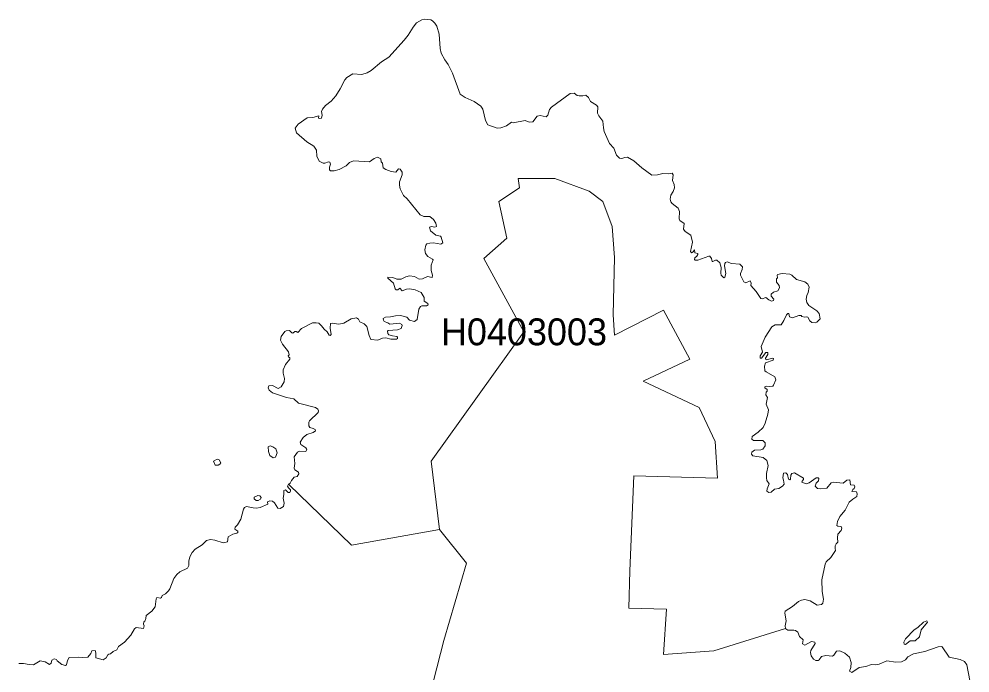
# Model space of a CAD drawing. Extents: x 369010 to 739155, y 6377141 to 6616555.
# Drawn here: x 422472 to 426007, y 6493936 to 6496369 of the extents above; entities that cross this region are included whole.
import ezdxf
from ezdxf.enums import TextEntityAlignment as Align

# ---------------------------------------------------------------- set-up
doc = ezdxf.new("R2010")
doc.units = 0
doc.header["$LTSCALE"] = 40
doc.layers.add('1', color=7, linetype='Continuous', lineweight=13)
doc.layers.add('2', color=7, linetype='Continuous')

msp = doc.modelspace()

# ---------------------------------------------------------------- linework, layer by layer
at = {"layer": '1'}
for points in [[(424682.77, 6495887.95), (424666.88, 6495905.17), (424646.53, 6495950.51), (424643.71, 6495963.92), (424642.39, 6495988.75), (424626.5, 6496008.77), (424622.36, 6496018.54), (424623.69, 6496042.37), (424618.89, 6496048.16), (424595.39, 6496062.06), (424588.6, 6496076.46), (424578.34, 6496085.4), (424567.91, 6496082.75), (424553.84, 6496082.75), (424546.23, 6496084.74), (424535.31, 6496092.68), (424520.25, 6496092.19), (424450.74, 6496040.88), (424443.12, 6496032.6), (424436.83, 6496010.76), (424430.71, 6496005.3), (424408.37, 6496009.6), (424398.27, 6496007.94), (424382.05, 6495986.43), (424367.65, 6495985.27), (424352.92, 6495991.73), (424309.06, 6495983.12), (424302.28, 6495984.61), (424283.41, 6495971.04), (424262.23, 6495963.92), (424248.66, 6495962.6), (424214.73, 6495974.68), (424205.13, 6495991.06), (424196.19, 6496032.94), (424187.75, 6496044.19), (424163.59, 6496062.06), (424130.32, 6496076.46), (424111.45, 6496088.88), (424083.48, 6496167.82), (424066.6, 6496199.27), (424054.02, 6496216.98), (424040.45, 6496241.47), (424037.14, 6496259.18), (424034, 6496312.14), (424024.56, 6496341.6), (424017.12, 6496353.35), (424008.34, 6496362.29), (424002.39, 6496365.1), (423980.04, 6496368.74), (423969.45, 6496366.26), (423949.75, 6496354.01), (423936.51, 6496338.62), (423918.47, 6496309.16), (423903.41, 6496290.13), (423845.98, 6496227.24), (423819.01, 6496209.03), (423780.61, 6496176.59), (423765.71, 6496168.48), (423746.52, 6496162.86), (423712.92, 6496165.17), (423690.24, 6496151.11), (423682.8, 6496142.5), (423665.75, 6496108.9), (423649.86, 6496082.92), (423632.15, 6496063.22), (423610.64, 6496047), (423599.55, 6496032.94), (423596.57, 6496024.16), (423598.39, 6496011.09), (423595.41, 6496000.5), (423586.8, 6495998.84), (423585.32, 6496000.17), (423585.98, 6496008.44), (423563.63, 6496001.99), (423542.45, 6496001.16), (423508.85, 6495977), (423498.26, 6495963.09), (423503.56, 6495945.22), (423541.46, 6495911.62), (423567.44, 6495896.23), (423577.21, 6495880.34), (423578.36, 6495858), (423587.47, 6495839.46), (423601.87, 6495832.68), (423608.98, 6495832.35), (423621.89, 6495836.98), (423627.19, 6495836.81), (423629.84, 6495829.04), (423625.37, 6495817.95), (423625.2, 6495808.18), (423629.01, 6495803.71), (423642.58, 6495803.71), (423661.94, 6495808.51), (423687.93, 6495822.91), (423700.01, 6495835.32), (423715.24, 6495840.62), (423773.82, 6495836.98), (423791.53, 6495850.39), (423804.44, 6495854.36), (423816.03, 6495848.9)], [(425399.57, 6495340.8), (425404.87, 6495351.56), (425408.34, 6495371.42), (425404.2, 6495382.67), (425392.12, 6495390.61), (425362, 6495400.05), (425343.8, 6495415.94), (425336.68, 6495419.74), (425308.38, 6495421.73), (425291, 6495417.92), (425289.51, 6495415.94), (425291, 6495406.5), (425287.19, 6495402.03), (425287.52, 6495390.28), (425297.29, 6495377.21), (425298.45, 6495368.44), (425292.82, 6495358.18), (425275.94, 6495352.22), (425267.17, 6495345.43), (425267.5, 6495338.15), (425277.43, 6495326.56), (425276.27, 6495321.1), (425268.99, 6495319.61), (425259.22, 6495324.25), (425247.97, 6495333.19), (425233.9, 6495328.39), (425228.94, 6495329.54), (425212.05, 6495355.2), (425191.86, 6495377.87), (425193.19, 6495386.64), (425189.38, 6495395.25), (425173.82, 6495386.97), (425165.88, 6495391.11), (425154.13, 6495415.61), (425153.8, 6495422.39), (425159.92, 6495437.45), (425160.58, 6495447.38), (425151.48, 6495456.82), (425120.53, 6495458.8), (425103.98, 6495465.09), (425098.19, 6495463.27), (425095.54, 6495459.8), (425094.22, 6495450.36), (425099.51, 6495422.06), (425095.54, 6495407.99), (425091.07, 6495406.17), (425082.13, 6495415.61), (425080.48, 6495422.72), (425081.31, 6495443.91), (425076.34, 6495462.11), (425065.75, 6495471.55), (425060.78, 6495471.55), (425051.02, 6495466.25), (425048.37, 6495467.08), (425046.05, 6495477.5), (425039.43, 6495486.28), (425036.29, 6495486.61), (424995.57, 6495471.55), (424984.98, 6495472.21), (424982.67, 6495474.53), (424983.33, 6495480.32), (424990.94, 6495486.61), (424994.91, 6495492.9), (424994.58, 6495496.7), (424984.32, 6495498.85), (424982.33, 6495509.94), (424977.87, 6495502.83), (424971.41, 6495498.69), (424968.27, 6495503.99), (424974.72, 6495538.74), (424969.09, 6495564.56), (424947.58, 6495578.13), (424941.95, 6495587.56), (424944.1, 6495607.59), (424927.88, 6495619.18), (424926.06, 6495625.3), (424926.73, 6495652.44), (424921.93, 6495665.35), (424899.58, 6495682.73), (424895.11, 6495688.69), (424892.3, 6495698.95), (424895.11, 6495713.02), (424903.39, 6495727.25), (424907.86, 6495740.82), (424906.7, 6495753.73), (424901.07, 6495767.8), (424903.06, 6495789.31), (424899.09, 6495795.27), (424887, 6495792.96), (424864.33, 6495794.28), (424844.8, 6495788.98), (424824.28, 6495787.49), (424787.37, 6495815.63), (424757.58, 6495841.45), (424733.42, 6495855.02), (424723.49, 6495854.19), (424712.23, 6495850.39), (424703.79, 6495850.55), (424692.21, 6495862.14), (424682.77, 6495887.95)], [(423816.03, 6495848.9), (423817.85, 6495837.97), (423822.48, 6495832.01), (423824.8, 6495814.64), (423834.56, 6495809.01), (423854.59, 6495802.06), (423872.63, 6495798.42), (423881.73, 6495810.83), (423888.68, 6495810.17), (423896.13, 6495798.75), (423896.13, 6495788.98), (423886.04, 6495763.16), (423885.54, 6495750.09), (423888.68, 6495737.18), (423901.43, 6495712.52), (423914.67, 6495700.11), (423962.17, 6495640.86), (423976.57, 6495634.73), (423999.24, 6495634.07), (424012.81, 6495622.98), (424020.43, 6495609.91), (424023.07, 6495596.67), (424017.78, 6495594.68), (424005.36, 6495597.33), (423996.92, 6495594.68), (424000.9, 6495580.45), (424021.25, 6495564.39), (424037.8, 6495560.42), (424040.78, 6495557.77), (424046.57, 6495535.76), (424039.29, 6495530.8), (424011.82, 6495536.26), (423998.91, 6495535.43), (423987.66, 6495531.96), (423983.35, 6495527.49), (423980.7, 6495509.78), (423982.69, 6495496.87), (423991.79, 6495484.79), (424008.84, 6495476.02), (424011.32, 6495472.7), (424003.05, 6495453.34), (424003.38, 6495433.81), (424008.84, 6495415.61), (424007.52, 6495407.33), (423990.14, 6495410.81), (423971.77, 6495402.86), (423959.52, 6495400.88), (423941.81, 6495411.47), (423922.94, 6495413.45), (423910.03, 6495409.65), (423892.33, 6495400.88), (423876.44, 6495401.21), (423860.71, 6495406.67), (423843.17, 6495408.82), (423843.17, 6495404.35), (423863.69, 6495386.15), (423869.98, 6495364.96), (423873.79, 6495361.16), (423879.25, 6495361.65), (423887.03, 6495366.95), (423896.46, 6495357.85), (423911.69, 6495363.97), (423924.76, 6495365.13), (423944.13, 6495360.82), (423965.97, 6495351.39), (423978.22, 6495333.35), (423977.73, 6495318.62), (423991.63, 6495310.18), (423992.46, 6495305.05), (423986, 6495301.24), (423968.79, 6495301.57), (423963.82, 6495299.26), (423958.2, 6495289.49), (423951.41, 6495251.59), (423941.15, 6495244.14), (423923.44, 6495247.95), (423913.51, 6495259.2), (423890.01, 6495265.33), (423871.14, 6495265), (423852.27, 6495260.36), (423834.23, 6495260.03), (423825.13, 6495255.07), (423825.96, 6495248.28), (423828.94, 6495243.81), (423842.51, 6495238.52), (423850.12, 6495233.22), (423886.37, 6495237.03), (423894.97, 6495232.06), (423896.46, 6495228.26), (423892.66, 6495217), (423878.75, 6495212.37), (423844, 6495210.05), (423841.68, 6495207.07), (423842.18, 6495198.46), (423846.65, 6495193.83), (423859.89, 6495189.69), (423876.44, 6495187.87), (423879.08, 6495184.89), (423877.93, 6495180.59), (423874.29, 6495177.94)], [(423473.93, 6494638.07), (423474.59, 6494637.57), (423707.13, 6494411.82), (424035.16, 6494469.42), (424003.87, 6494724.3), (424348.62, 6495205.08), (424199.67, 6495477.34), (424284.74, 6495553.97), (424254.94, 6495690.18), (424331.57, 6495741.15), (424327.27, 6495775.25), (424463.48, 6495775.25), (424591.08, 6495728.41), (424642.22, 6495690.18), (424676.15, 6495596.5), (424684.76, 6495481.64), (424680.46, 6495268.8), (424684.76, 6495192.34), (424867.64, 6495285.85), (424965.62, 6495102.97), (424791.18, 6495022.04), (424999.55, 6494924.22), (425059.13, 6494796.62), (425067.73, 6494660.41), (424757.08, 6494668.85), (424742.19, 6494315.83), (424737.89, 6494177.47), (424878.4, 6494173.17), (424867.64, 6494005.18), (425054.99, 6494017.92), (425321.29, 6494101.34), (425321.45, 6494101.5), (425319.96, 6494110.94), (425323.93, 6494129.81), (425317.98, 6494158.27), (425319.3, 6494166.05), (425346.44, 6494183.43), (425368.62, 6494201.97), (425380.37, 6494207.26), (425392.12, 6494209.25), (425412.15, 6494204.28), (425438.46, 6494188.39), (425454.19, 6494190.55), (425459.15, 6494195.84), (425461.97, 6494210.24), (425457.17, 6494239.53), (425456.17, 6494282.07), (425467.92, 6494340.82), (425472.06, 6494349.26), (425488.78, 6494365.65), (425506.49, 6494391.96), (425505.82, 6494399.08), (425505.82, 6494408.85), (425508.64, 6494416.29), (425515.42, 6494422.91), (425513.77, 6494438.3), (425515.75, 6494451.88), (425527.5, 6494466.28), (425529.82, 6494474.55), (425528.17, 6494480.51), (425515.75, 6494481.67), (425511.62, 6494484.48), (425513.93, 6494500.2), (425522.54, 6494518.08), (425542.23, 6494542.24), (425557.96, 6494571.37), (425571.2, 6494582.96), (425585.93, 6494592.06), (425587.58, 6494601.99), (425584.44, 6494610.26), (425567.89, 6494611.26), (425570.54, 6494618.87), (425576.49, 6494621.85), (425578.81, 6494628.3), (425576.49, 6494634.76), (425561.93, 6494636.58), (425559.94, 6494654.78), (425548.69, 6494653.63), (425534.95, 6494642.7), (425499.2, 6494646.51), (425490.43, 6494643.03), (425474.87, 6494623.83), (425451.54, 6494621.19), (425439.79, 6494622.68), (425430.68, 6494630.62), (425435.32, 6494642.37), (425443.59, 6494651.47), (425444.26, 6494659.25), (425442.1, 6494662.4), (425434.49, 6494662.23), (425409.17, 6494643.36), (425397.42, 6494639.72), (425382.03, 6494645.35), (425382.36, 6494649.16), (425387.32, 6494655.61), (425387.32, 6494660.91), (425354.06, 6494680.44), (425344.13, 6494678.29), (425341.15, 6494671.5), (425339.66, 6494656.6)], [(426006.64, 6493908.53), (425995.55, 6493965.96), (425986.78, 6493978.37), (425970.06, 6493986.48), (425929.35, 6493995.09), (425903.2, 6494033.48), (425899.56, 6494035.14), (425887.81, 6494033.81), (425838.82, 6494015.61), (425796.78, 6494007.5), (425776.09, 6493995.75), (425766.33, 6493985.49), (425752.59, 6493978.04), (425731.07, 6493976.71), (425697.48, 6493981.68), (425669.01, 6493968.6), (425654.61, 6493966.29), (425640.38, 6493967.28), (425620.02, 6493959.83), (425594.2, 6493956.19), (425567.23, 6493937.66), (425558.78, 6493942.62), (425563.58, 6493956.19), (425565.57, 6493975.06), (425559.28, 6493995.42), (425541.41, 6494009.98), (425523.37, 6494018.26), (425510.29, 6494017.26), (425500.53, 6494002.2), (425495.4, 6493998.89), (425471.23, 6494000.55), (425455.18, 6493997.07), (425446.41, 6493985.32), (425441.77, 6493982.67), (425433.33, 6493982.67), (425425.06, 6493987.14), (425416.29, 6493999.88), (425414.3, 6494012.3), (425415.29, 6494020.24), (425431.02, 6494046.23), (425429.69, 6494051.19), (425417.94, 6494053.18), (425392.12, 6494039.77), (425383.68, 6494044.41), (425386, 6494059.96), (425372.59, 6494072.38), (425366.63, 6494088.1), (425358.19, 6494093.89), (425351.74, 6494095.55), (425329.73, 6494095.22), (425321.62, 6494100.84), (425321.45, 6494101.5), (425321.29, 6494101.34), (425054.99, 6494017.92), (424867.64, 6494005.18), (424878.4, 6494173.17), (424737.89, 6494177.47), (424742.19, 6494315.83), (424757.08, 6494668.85), (425067.73, 6494660.41), (425059.13, 6494796.62), (424999.55, 6494924.22), (424791.18, 6495022.04), (424965.62, 6495102.97), (424867.64, 6495285.85), (424684.76, 6495192.34), (424680.46, 6495268.8), (424684.76, 6495481.64), (424676.15, 6495596.5), (424642.22, 6495690.18), (424591.08, 6495728.41), (424463.48, 6495775.25), (424327.27, 6495775.25), (424331.57, 6495741.15), (424254.94, 6495690.18), (424284.74, 6495553.97), (424199.67, 6495477.34), (424348.62, 6495205.08), (424003.87, 6494724.3), (424035.16, 6494469.42), (424135.45, 6494344.13), (424050.22, 6494056.82), (423846.31, 6493258.43)], [(425339.66, 6494656.6), (425337.34, 6494654.12), (425332.54, 6494656.6), (425327.91, 6494674.81), (425322.61, 6494680.11), (425313.67, 6494679.78), (425311.03, 6494661.57), (425314, 6494653.96), (425315.49, 6494638.56), (425309.87, 6494630.62), (425295.47, 6494622.18), (425280.08, 6494619.7), (425267.5, 6494608.77), (425258.56, 6494607.45), (425251.94, 6494612.91), (425252.44, 6494621.52), (425260.71, 6494639.23), (425251.94, 6494652.14), (425249.79, 6494662.23), (425250.45, 6494678.62), (425256.57, 6494707.58), (425251.61, 6494726.61), (425237.71, 6494737.54), (425199.81, 6494744.32), (425195.01, 6494749.95), (425195.34, 6494757.23), (425205.93, 6494764.35), (425229.43, 6494765.84), (425236.55, 6494768.49), (425245.15, 6494781.23), (425245.15, 6494791.99), (425236.55, 6494800.59), (425201.46, 6494800.59), (425195.67, 6494805.89), (425197.16, 6494815.32), (425219.83, 6494831.54), (425237.38, 6494849.42), (425244.82, 6494865.97), (425254.59, 6494898.9), (425257.24, 6494914.79), (425249.29, 6494935.48), (425253.6, 6494961.13), (425247.47, 6494970.23), (425248.63, 6494980.5), (425252.11, 6494984.3), (425252.11, 6494990.59), (425243.83, 6494996.22), (425243.83, 6495000.85), (425249.46, 6495003.5), (425260.05, 6495001.68), (425273.62, 6495003.5), (425276.6, 6495006.15), (425284.54, 6495026.18), (425281.57, 6495037.93), (425248.63, 6495056.3), (425244.49, 6495060.43), (425242.18, 6495077.48), (425246.81, 6495089.89), (425275.28, 6495099.49), (425276.6, 6495105.62), (425271.3, 6495106.61), (425251.61, 6495100.49), (425246.31, 6495103.13), (425246.48, 6495106.94), (425255.75, 6495121.01), (425255.75, 6495126.64), (425253.6, 6495128.62), (425247.47, 6495128.62), (425231.58, 6495107.44), (425227.11, 6495107.77), (425226.78, 6495115.22), (425235.89, 6495129.62), (425230.42, 6495150.8), (425244.82, 6495185.89), (425269.48, 6495223.62), (425281.9, 6495230.57), (425305.23, 6495231.73), (425315.16, 6495247.12), (425325.09, 6495268.14), (425329.56, 6495272.94), (425332.87, 6495272.94), (425335.19, 6495260.36), (425346.77, 6495256.89), (425370.28, 6495265.66), (425379.38, 6495265.99), (425381.7, 6495262.68), (425392.29, 6495260.03), (425400.56, 6495261.52), (425404.2, 6495260.03), (425411.16, 6495245.63), (425419.1, 6495239.68), (425431.02, 6495239.18), (425436.81, 6495241.16), (425450.05, 6495253.58), (425445.75, 6495272.78), (425436.81, 6495283.7), (425408.01, 6495303.06), (425400.23, 6495314.32), (425397.91, 6495327.23), (425399.57, 6495340.8)], [(423874.29, 6495177.94), (423853.43, 6495177.28), (423835.23, 6495182.25), (423822.15, 6495181.42), (423805.44, 6495174.63), (423779.78, 6495176.95), (423773, 6495191.18), (423765.05, 6495224.45), (423754.46, 6495234.38), (423738.9, 6495241.83), (423733.61, 6495251.76), (423726.16, 6495257.05), (423706.8, 6495253.25), (423678.99, 6495237.36), (423660.12, 6495234.21), (423635.96, 6495237.36), (423629.84, 6495236.2), (423628.68, 6495218.82), (423632.15, 6495194.66), (423627.85, 6495190.85), (423624.21, 6495192.67), (423616.93, 6495204.75), (423605.34, 6495215.35), (423595.74, 6495227.92), (423585.65, 6495236.86), (423575.88, 6495239.18), (423562.97, 6495238.52), (423522.26, 6495217.17), (423508.19, 6495202.27), (423502.07, 6495206.74), (423497.27, 6495206.41), (423489.65, 6495200.62), (423485.52, 6495201.44), (423477.57, 6495210.05), (423464.66, 6495209.39), (423460.19, 6495206.41), (423446.62, 6495187.54), (423443.48, 6495174.63), (423450.76, 6495159.57), (423473.77, 6495130.77), (423475.26, 6495119.52), (423472.61, 6495116.04), (423473.43, 6495112.57), (423478.73, 6495108.43), (423478.73, 6495103.13), (423461.68, 6495083.27), (423453.74, 6495063.91), (423453.74, 6495051), (423457.88, 6495031.47), (423456.72, 6495018.56), (423446.29, 6495000.85), (423435.2, 6494994.4), (423414.02, 6495004.99), (423400.45, 6495004.16), (423397.8, 6494997.38), (423401.27, 6494987.94), (423414.18, 6494978.18), (423465.82, 6494961.46), (423493.13, 6494955.84), (423510.51, 6494940.28), (423574.23, 6494924.22), (423582.67, 6494916.94), (423584.82, 6494910.82), (423583.99, 6494904.53), (423551.55, 6494874.24), (423549.4, 6494869.44), (423548.9, 6494856.04), (423552.71, 6494849.42), (423564.79, 6494845.94), (423572.07, 6494841.31), (423573.23, 6494836.84), (423564.79, 6494830.38), (423540.96, 6494823.27), (423527.89, 6494811.52), (423517.13, 6494794.64), (423519.44, 6494786.19), (423537.98, 6494774.11), (423541.79, 6494767.66), (423537.15, 6494760.21), (423514.64, 6494761.37), (423506.2, 6494757.56), (423494.95, 6494739.69), (423497.1, 6494715.69), (423494.95, 6494697.48), (423497.1, 6494691.86), (423510.01, 6494683.09), (423511.17, 6494676.3), (423505.21, 6494667.53), (423493.79, 6494664.88), (423484.36, 6494652.14), (423479.56, 6494641.87), (423474.26, 6494638.56), (423473.93, 6494638.07)], [(423473.93, 6494638.07), (423469.63, 6494631.45), (423472.94, 6494624.5), (423480.55, 6494617.05), (423481.05, 6494613.24), (423478.23, 6494607.62), (423471.94, 6494607.45), (423462.01, 6494617.05), (423456.06, 6494615.39), (423456.06, 6494599.67), (423453.08, 6494586.76), (423457.22, 6494567.4), (423455.23, 6494555.81), (423442.32, 6494547.37), (423433.38, 6494549.36), (423420.8, 6494569.05), (423414.02, 6494575.51), (423403.43, 6494576.5), (423394.82, 6494572.86), (423396.31, 6494563.76), (423367.51, 6494551.34), (423354.44, 6494549.36), (423341.53, 6494550.02), (423317.36, 6494555.48), (423309.75, 6494551.18), (423305.94, 6494546.05), (423296.51, 6494507.82), (423283.27, 6494486.96), (423275.16, 6494478.69), (423274, 6494470.74), (423284.43, 6494463.3), (423284.43, 6494458.99), (423281.45, 6494456.34), (423265.89, 6494452.7), (423249.51, 6494442.94), (423246.36, 6494424.07), (423230.64, 6494420.76), (423199.19, 6494430.53), (423183.64, 6494432.51), (423167.91, 6494428.37), (423152.52, 6494412.32), (423126.21, 6494396.93), (423115.28, 6494383.85), (423106.84, 6494368.3), (423102.54, 6494352.57), (423102.87, 6494335.53), (423097.74, 6494326.42), (423068.94, 6494312.03), (423057.85, 6494302.92), (423046.77, 6494287.86), (423032.04, 6494248.8), (423027.57, 6494241.19), (423016.48, 6494230.43), (423004.07, 6494223.98), (423001.75, 6494217.36), (422997.11, 6494213.88), (422984.37, 6494217.36), (422981.23, 6494212.23), (422977.25, 6494181.77), (422965.5, 6494166.38), (422944.32, 6494149.83), (422943.33, 6494139.07), (422939.35, 6494129.31), (422935.38, 6494126.33), (422933.89, 6494117.72), (422936.71, 6494111.27), (422933.89, 6494102.17), (422907.41, 6494105.31), (422901.45, 6494100.84), (422887.05, 6494076.35), (422864.21, 6494050.2), (422841.04, 6494034.48), (422834.59, 6494022.39), (422821.51, 6494016.6), (422812.08, 6494006.84), (422805.79, 6494006.17), (422802.15, 6494003.53), (422795.7, 6493992.44), (422784.11, 6493985.65), (422757.3, 6493992.93), (422757.46, 6494010.97), (422754.49, 6494020.24), (422742.4, 6494017.92), (422738.6, 6494008.82), (422727.84, 6493995.09), (422707.48, 6493993.1), (422691.26, 6493994.75), (422658.49, 6493993.43), (422651.71, 6493982.01), (422647.74, 6493966.62), (422643.93, 6493963.64), (422631.18, 6493967.28), (422613.48, 6493981.02), (422611.16, 6493985.82), (422602.06, 6493988.47), (422593.28, 6493984), (422590.97, 6493973.24), (422585.17, 6493967.61), (422569.12, 6493978.04), (422549.59, 6493981.35)], [(423846.31, 6493258.43), (424050.22, 6494056.82), (424135.45, 6494344.13), (424035.16, 6494469.42), (423707.13, 6494411.82), (423474.59, 6494637.57), (423473.93, 6494638.07)], [(422549.59, 6493981.35), (422524.77, 6493966.62), (422509.04, 6493967.28), (422488.19, 6493971.91), (422470.48, 6493971.25)]]:
    msp.add_lwpolyline(points, dxfattribs=at)
for points in [[(423416.34, 6494737.04), (423424.94, 6494739.36), (423431.07, 6494755.08), (423426.43, 6494769.81), (423415.67, 6494777.59), (423404.75, 6494780.9), (423397.96, 6494776.93), (423398.96, 6494759.88), (423404.09, 6494745.65)], [(423207.8, 6494731.41), (423194.39, 6494724.46), (423200.19, 6494709.4), (423211.61, 6494708.9), (423218.23, 6494712.38), (423221.21, 6494718.34), (423215.91, 6494729.43)], [(423359.4, 6494595.7), (423345.17, 6494590.4), (423345.5, 6494583.78), (423353.44, 6494577.49), (423361.06, 6494577.16), (423369.83, 6494582.96), (423371.15, 6494588.75), (423366.35, 6494594.54)], [(425846.43, 6494129.64), (425834.02, 6494125.34), (425812.67, 6494104.98), (425799.1, 6494096.37), (425766.66, 6494063.6), (425761.03, 6494050.36), (425762.02, 6494043.74), (425766.66, 6494042.42), (425784.04, 6494055.99), (425803.4, 6494056.32), (425818.63, 6494070.06), (425825.41, 6494096.37), (425848.75, 6494125.01)]]:
    msp.add_lwpolyline(points, close=True, dxfattribs=at)

# ---------------------------------------------------------------- texts
at = {"layer": '2'}
msp.add_text('H0403003', height=100, dxfattribs=at).set_placement((424348.61, 6495155.08), align=Align.CENTER)

doc.saveas('drawing.dxf')
